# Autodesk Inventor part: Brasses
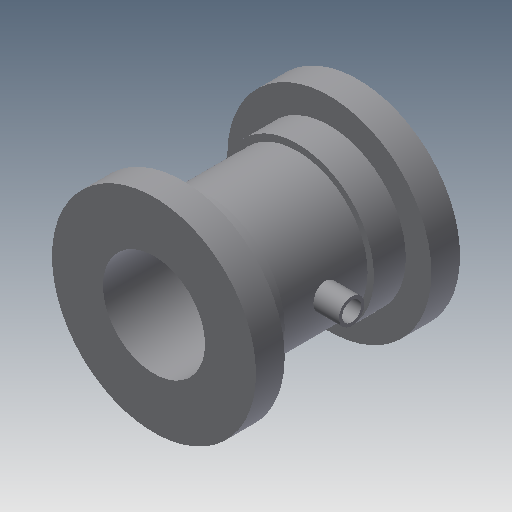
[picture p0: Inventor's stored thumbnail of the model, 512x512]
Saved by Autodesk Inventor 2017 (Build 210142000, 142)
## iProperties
Created: 2009-04
Part Number: Brasses
Document SubType Name: Modeling
Designer: Sham
Density: 1 g/cm^3
Material: Generic
Appearance: Default
Author: Sham
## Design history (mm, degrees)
sketch "Sketch1"
  geometry: L1 (0, 32)-(9, 32); L2 (0, 16)-(64, 16); L3 (64, 32)-(55, 32); L4 (55, 32)-(55, 24); L5 (55, 24)-(47, 24); L6 (19, 22)-(47, 22); L7 (47, 24)-(47, 22); L8 (19, 22)-(19, 24); L9 (19, 24)-(9, 24); L10 (9, 24)-(9, 32); L11 (0, 32)-(0, 16); L12 (64, 32)-(64, 16); L13 (-12.8, 0)-(76.8, 0) reference; 1 further point
  constraints: 24 end point, 7 parallel, 4 perpendicular, 1 collinear, 1 horizontal, 1 vertical alignment, 1 other
  dimensions: "d0" = 9 distance of L1.start L1.end; "d2" = 16 distance from line of L2 point (0, 0); "d3" = 64 distance of L2.start L2.end; "d4" = 24 distance from line of point (0, 0) L5; "d5" = 28 distance of L6.start L6.end; "d6" = 22 distance from line of point (0, 0) L6; "d7" = 8 distance of L4.end L5.end
revolve "Revolution1" sketch "Sketch1" stored, may be unused: angle "d8" = 90 deg
workplane "Work Plane1"
sketch "Sketch2"
  geometry: C1 r 4 at (-32, 0)
  constraints: 1 centre point
  dimensions: "d10" = 8 diameter of C1
extrude "Extrusion1" join sketch "Sketch2" stored distance "d11" = 10; taper "d12" = 0 deg
sketch "Sketch3"
  geometry: C1 r 4 at (0, 0) reference; C2 r 3 at (0, 0)
  constraints: 1 centre point, 1 coincident
  dimensions: "d13" = 6 diameter of C2
extrude "Extrusion2" cut sketch "Sketch3" stored distance "d14" = 10; taper "d15" = 0 deg
body "Solid1"
